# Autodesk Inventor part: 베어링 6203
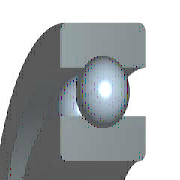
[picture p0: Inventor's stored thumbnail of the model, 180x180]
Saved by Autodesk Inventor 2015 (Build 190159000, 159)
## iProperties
IsCustomPart: 0
Created: 2009-02
Part Number: 베어링 6203
Material: 강철, 연강
Description: 깊은 그루브 볼 베어링
Document SubType Name: Modeling
Standard: KS B 2023
Standards Organization: KS
Language: ko-KR
Size Designation: 6203 - 17 x 40 x 12
Categories: <MemberInstance><Categories><Category DisplayName="샤프트 부품" InternalName="7f7aeb1f-a693-4053-b835-cee3144e0d98" Mnemonic="SHFT"><Category DisplayName="베어링" Inter
Density: 1 g/cm^3
Appearance: 밝은 황색
Author: pww
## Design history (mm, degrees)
sketch "스케치" dims "d0" = 5.98 (= -0.26 x WD + 0.26 x BD)
  geometry: L1 (3.01, 14.25)-(8.99, 14.25); L2 (6, 14.25)-(6, 11.26); L3 (6, 14.25)-(6, 17.24); L4 (3.778, 12.249)-(0, 12.249); L5 (0, 8.5)-(12, 8.5); L6 (3.778, 16.251)-(0, 16.251); L7 (0, 20)-(12, 20); L8 (12, 8.5)-(12, 12.249); L9 (8.222, 12.249)-(12, 12.249); L10 (8.222, 16.251)-(12, 16.251); L11 (12, 20)-(12, 16.251); L12 (-1.4, 0)-(8.4, 0) reference; L13 (0, -0.3)-(0, 5.3) reference
  constraints: 22 end point, 4 point on line, 2 collinear, 2 perpendicular, 2 symmetric about line, 1 midpoint, 1 parallel, 14 other
  dimensions: "d9" = 17 diameter of L5 L12 (= WD); "d11" = 40 diameter of L7 L12 (= BD); "d12" = 12 distance between parallel lines of L8 L13 (= KB); "d13" = 24.498 diameter of L9 L12 (= 0.326 x BD + 0.674 x WD)
revolve "본체" stored, may be unused: angle "d6" = 90 deg
revolve "볼" stored, may be unused: angle "d7" = 90 deg
pattern_circular "IDS_ARRAYBALL[SIMPL:T]" dims angle "d3" = 360 deg
body "Solid1"
fillet "모깎기1" dims "d1" = 0.6 (= KRS)
other parameters: "WD" = 17 [user parameter; used in 5 equation terms], "BD" = 40 [user parameter; used in 5 equation terms], "KB" = 12 [user parameter; used in 1 equation term], "KRS" = 0.6 [user parameter; used in 1 equation term], "d4" = 0, "d5" = 0, "d8" = 0, "d14" = 0, "d15" = 0, "BBA" = 0 [user parameter], "BC0" = 4750000 [user parameter], "BC" = 9560000 [user parameter], "WR" = 8.5 (= 0.5 x WD) [user parameter]
